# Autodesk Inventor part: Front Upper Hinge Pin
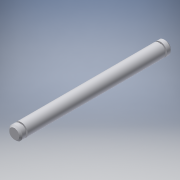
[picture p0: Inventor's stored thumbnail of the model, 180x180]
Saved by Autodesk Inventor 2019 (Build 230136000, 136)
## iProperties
Shininess: 50.0
Compacted: True
Length Units: 11272
Angle Units: 11279
Time Units: 11290
Mass Units: 11286
Length Display Precision: 4
Angle Display Precision: 2
Company: Autodesk
Created: 2000-06
Part Number: Front Upper Hinge Pin
Project: Inventor Samples
Document SubType Name: Modeling
Designer: Autodesk, Inc.
Density: 2.71 g/cm^3
Material: Aluminum-6061
Mass: 0.768459 g
Surface Area: 3.85189 cm^2
Volume: 0.283564 cm^3
Appearance: Light Grey
Density: 0.0
Volumn: 0.0
Area: 0.0
PropertySet Name: Model Information
Control State: 0
Master: False
Checked Out: False
Checked Out Date: 2018-05-30
Last Check In Date: 2018-05-30
Author: Autodesk, Inc.
Revision Number: A
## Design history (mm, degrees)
node "Extrusion1" dims "d1" = 33.01492, "d2" = 0
  sketch "Sketch2"
    geometry: C1 r 1.587 at (-3.385, 8.562)
    constraints: 1 centre point
    dimensions: "d0" = 3.175 diameter of C1
node "Extrusion2" dims "d4" = 0.381, "d5" = 0
  sketch "Sketch3"
    geometry: C1 r 1.587 at (0, 0) reference; C2 r 1.191 at (0, 0)
    constraints: 1 centre point, 1 coincident
    dimensions: "d3" = 2.38252 diameter of C2
node "Extrusion3" dims "d6" = 1.27, "d7" = 0
  sketch "Sketch4"
    geometry: C1 r 1.587 at (0, 0) reference
node "Chamfer1" dims "d8" = 0.381, "d9" = 0.381, "d17" = 45 deg
node "Extrusion4" dims "d11" = 0.381, "d12" = 0
  sketch "Sketch5"
    geometry: C1 r 1.587 at (0, 0) reference; C2 r 1.191 at (0, 0)
    constraints: 1 centre point, 1 coincident
    dimensions: "d10" = 2.38252 diameter of C2
node "Extrusion5" dims "d13" = 1.27, "d14" = 0
  sketch "Sketch6"
    geometry: C1 r 1.587 at (0, 0) reference
node "Chamfer2" dims "d15" = 0.381, "d16" = 0.381, "d18" = 45 deg
body "Solid1"
